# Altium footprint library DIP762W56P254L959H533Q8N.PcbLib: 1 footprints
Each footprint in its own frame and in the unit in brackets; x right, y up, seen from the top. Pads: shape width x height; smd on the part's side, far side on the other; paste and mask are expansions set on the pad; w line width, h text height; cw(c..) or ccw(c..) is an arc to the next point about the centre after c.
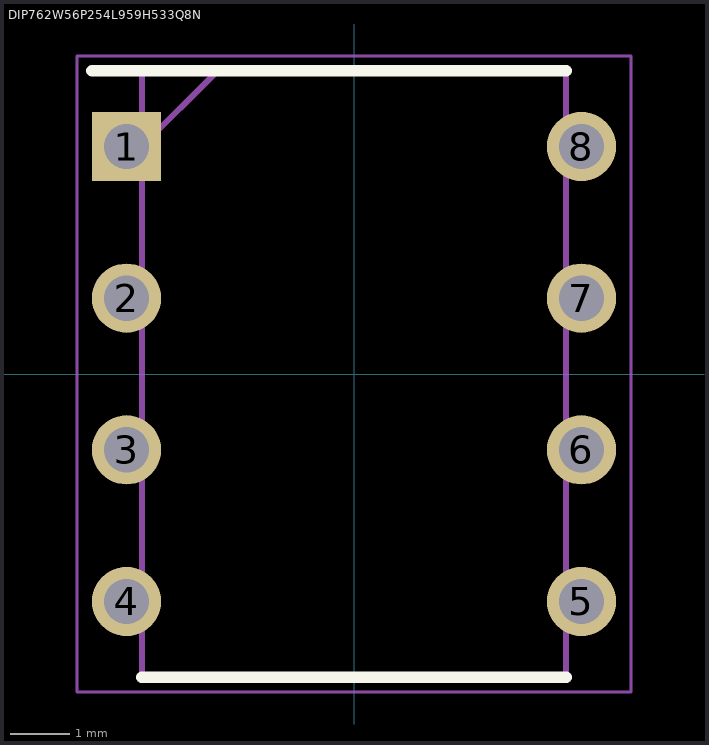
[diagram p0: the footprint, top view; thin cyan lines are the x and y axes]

## DIP762W56P254L959H533Q8N [mm]
pads (8):
  rect 1.16x1.16 / inner round 1.16 / far side rect 1.16x1.16 hole 0.76: 1(-3.81,3.81)
  round 1.16 hole 0.76: 2(-3.81,1.27) 3(-3.81,-1.27) 4(-3.81,-3.81) 5(3.81,-3.81) 6(3.81,-1.27) 7(3.81,1.27) 8(3.81,3.81)
Top Overlay:
  lines w0.2: -4.39,5.08 3.555,5.08 ; -3.555,-5.08 3.555,-5.08
Mechanical 15:
  lines w0.1: -3.555,3.81 -2.285,5.08 ; -3.555,-5.08 3.555,-5.08 3.555,5.08 -3.555,5.08 -3.555,-5.08
Mechanical 20:
  lines w0.05: -4.64,-5.33 4.64,-5.33 4.64,5.33 -4.64,5.33 -4.64,-5.33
